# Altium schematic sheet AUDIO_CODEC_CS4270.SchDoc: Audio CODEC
size A4; DocumentNumber: 5; SheetNumber: 5; SheetTotal: 100; Organization: Altium Limited.; Address1: Level 3, 12a Rodborough Rd; Address2: Frenchs Forest 2086; Address3: NSW; Address4: AUSTRALIA
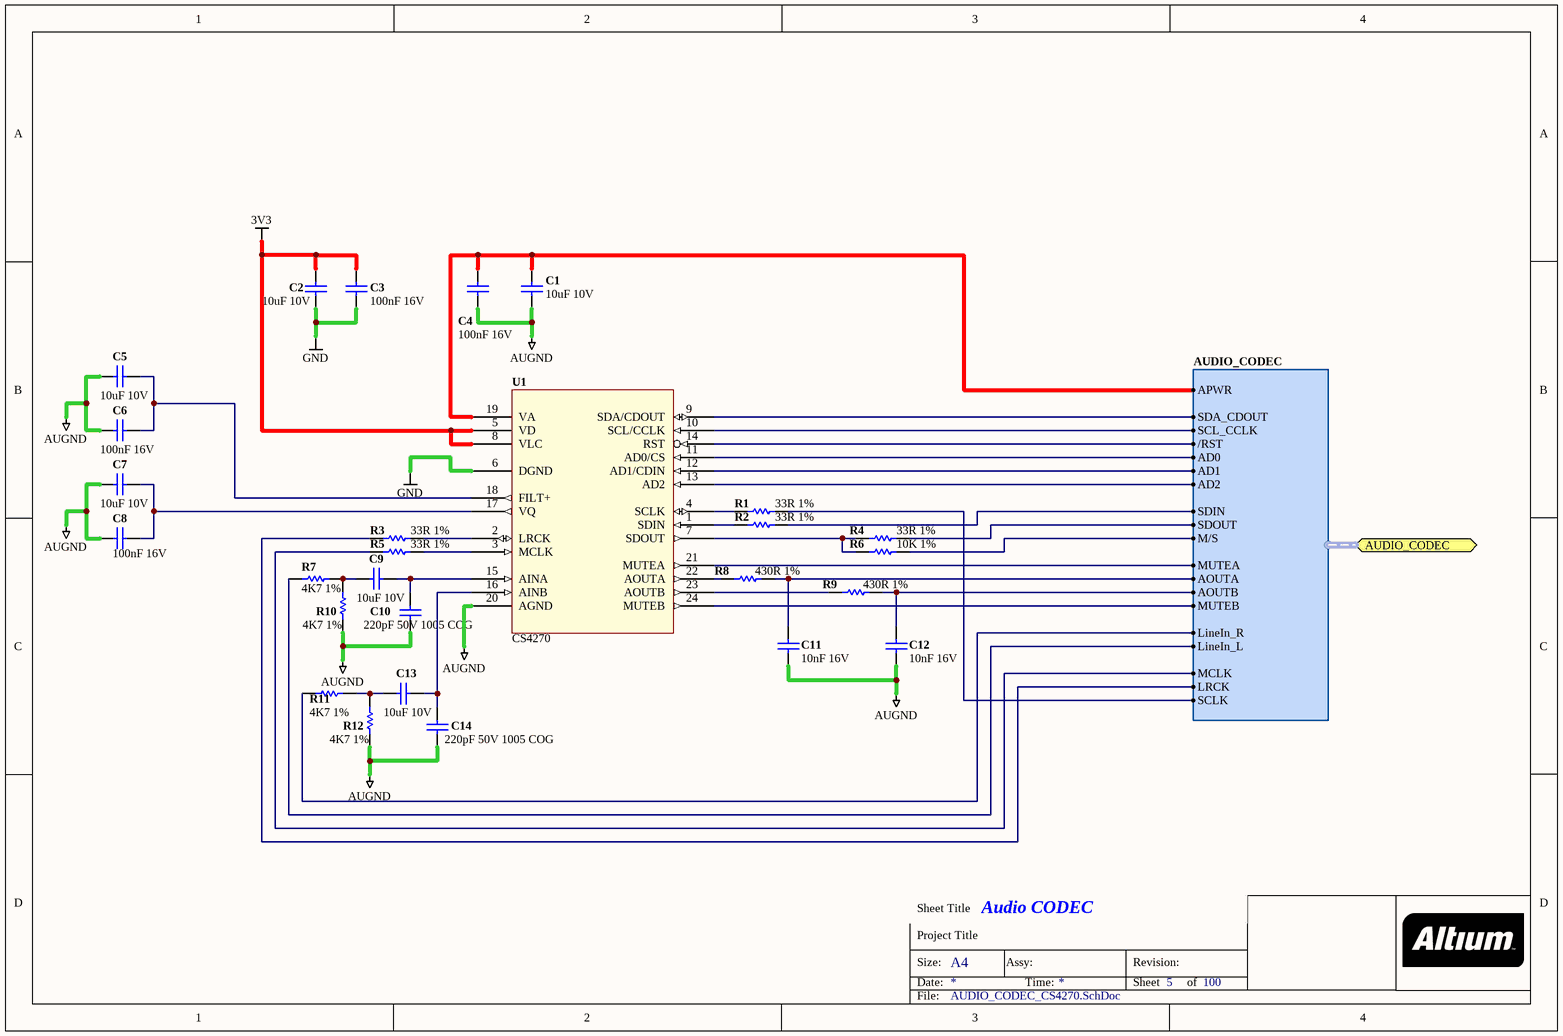
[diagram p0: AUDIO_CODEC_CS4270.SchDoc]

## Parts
C1  10uF 10V  [CAPC2012-STAR]
C2  10uF 10V  [CAPC2012-STAR]
C3  100nF 16V  [CAPC1005-STAR]
C4  100nF 16V  [CAPC1005-STAR]
C5  10uF 10V  [CAPC2012-STAR]
C6  100nF 16V  [CAPC1005-STAR]
C7  10uF 10V  [CAPC2012-STAR]
C8  100nF 16V  [CAPC1005-STAR]
C9  10uF 10V  [CAPC2012-STAR]
C10  220pF 50V 1005 COG  [CAPC1005-STAR]
C11  10nF 16V  [CAPC1005-STAR]
C12  10nF 16V  [CAPC1005-STAR]
C13  10uF 10V  [CAPC2012-STAR]
C14  220pF 50V 1005 COG  [CAPC1005-STAR]
R1  33R 1%  [RESC1005-STAR]
R2  33R 1%  [RESC1005-STAR]
R3  33R 1%  [RESC1005-STAR]
R4  33R 1%  [RESC1005-STAR]
R5  33R 1%  [RESC1005-STAR]
R6  10K 1%  [RESC1005-STAR]
R7  4K7 1%  [RESC1005-STAR]
R8  430R 1%  [RESC1005-STAR]
R9  430R 1%  [RESC1005-STAR]
R10  4K7 1%  [RESC1005-STAR]
R11  4K7 1%  [RESC1005-STAR]
R12  4K7 1%  [RESC1005-STAR]
U1  CS4270  [TSSOP-24]

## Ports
AUDIO_CODEC (harness AUDIO_CODEC)

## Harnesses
AUDIO_CODEC: SDOUT, SDIN, SCLK, LRCK, MCLK, M/S, LineIn_L, LineIn_R, AOUTA, AOUTB, APWR, SCL_CCLK, AD1, SDA_CDOUT, AD0, AD2, /RST, MUTEA, MUTEB

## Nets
3V3: C2.1 C3.1 U1.5(VD) U1.8(VLC)
AUGND: C1.2 C4.2 C5.2 C6.1 C7.2 C8.2 C10.2 C11.2 C12.2 C14.2 R10.1 R12.1 U1.20(AGND)
GND: C2.2 C3.2 U1.6(DGND)
NetC1_1: C1.1 C4.1 U1.19(VA) ; port AUDIO_CODEC.APWR
NetC5_1: C5.1 C6.2 U1.18(FILT+)
NetC7_1: C7.1 C8.1 U1.17(VQ)
NetC9_1: C9.1 C10.1 U1.15(AINA)
NetC9_2: C9.2 R7.2 R10.2
NetC11_1: C11.1 R8.1 ; port AUDIO_CODEC.AOUTA
NetC12_1: C12.1 R9.1 ; port AUDIO_CODEC.AOUTB
NetC13_1: C13.1 C14.1 U1.16(AINB)
NetC13_2: C13.2 R11.2 R12.2
NetR1_1: R1.1 U1.4(SCLK)
NetR1_2: R1.2 ; port AUDIO_CODEC.SCLK
NetR2_1: R2.1 U1.1(SDIN)
NetR2_2: R2.2 ; port AUDIO_CODEC.SDIN
NetR3_1: R3.1 ; port AUDIO_CODEC.LRCK
NetR3_2: R3.2 U1.2(LRCK)
NetR4_1: R4.1 R6.2 U1.7(SDOUT)
NetR4_2: R4.2 ; port AUDIO_CODEC.SDOUT
NetR5_1: R5.1 ; port AUDIO_CODEC.MCLK
NetR5_2: R5.2 U1.3(MCLK)
NetR6_1: R6.1 ; port AUDIO_CODEC.M/S
NetR7_1: R7.1 ; port AUDIO_CODEC.LineIn_L
NetR8_2: R8.2 U1.22(AOUTA)
NetR9_2: R9.2 U1.23(AOUTB)
NetR11_1: R11.1 ; port AUDIO_CODEC.LineIn_R
NetU1_9: U1.9(SDA/CDOUT) ; port AUDIO_CODEC.SDA_CDOUT
NetU1_10: U1.10(SCL/CCLK) ; port AUDIO_CODEC.SCL_CCLK
NetU1_11: U1.11(AD0/CS) ; port AUDIO_CODEC.AD0
NetU1_12: U1.12(AD1/CDIN) ; port AUDIO_CODEC.AD1
NetU1_13: U1.13(AD2) ; port AUDIO_CODEC.AD2
NetU1_14: U1.14(RST) ; port AUDIO_CODEC./RST
NetU1_21: U1.21(MUTEA) ; port AUDIO_CODEC.MUTEA
NetU1_24: U1.24(MUTEB) ; port AUDIO_CODEC.MUTEB

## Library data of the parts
C1 C2 C5 C7 C9 C13 = D-101-0087: Capacitor, Ceramic, 10uF 10% 10V 0805 (2012) X5R; Polarity: Non-Polarized
C3 C4 C6 C8 = D-101-0062: Capacitor, Ceramic, 100nF 10% 16V 0402 (1005) X7R; Polarity: Non-Polarized
C10 C14 = D-101-0064: Capacitor, Ceramic, 220pF 5% 50V 0402 (1005) COG; Polarity: Non-Polarized
C11 C12 = D-101-0077: Capacitor, Ceramic, 10nF 10% 16V 0402 (1005) X7R; Polarity: Non-Polarized
R1-R5 = D-100-0102: Resistor, 33R 1% 0402 (1005); Power Rating: 63 mW
R6 = D-100-0130: Resistor, 10K 1% 0402 (1005); Power Rating: 63 mW
R7 R10-R12 = D-100-0088: Resistor, 4K7 1% 0402 (1005); Power Rating: 63 mW; Resistance: 4.7 K
R8 R9 = D-100-0096: Resistor, 430R 1% 0402 (1005); Power Rating: 63 mW
U1 = D-201-0003: CS4270; 24-Bit, 192 kHz Stereo Audio CODEC; AudioICTypes: Amplifier; Supply Voltage: mV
